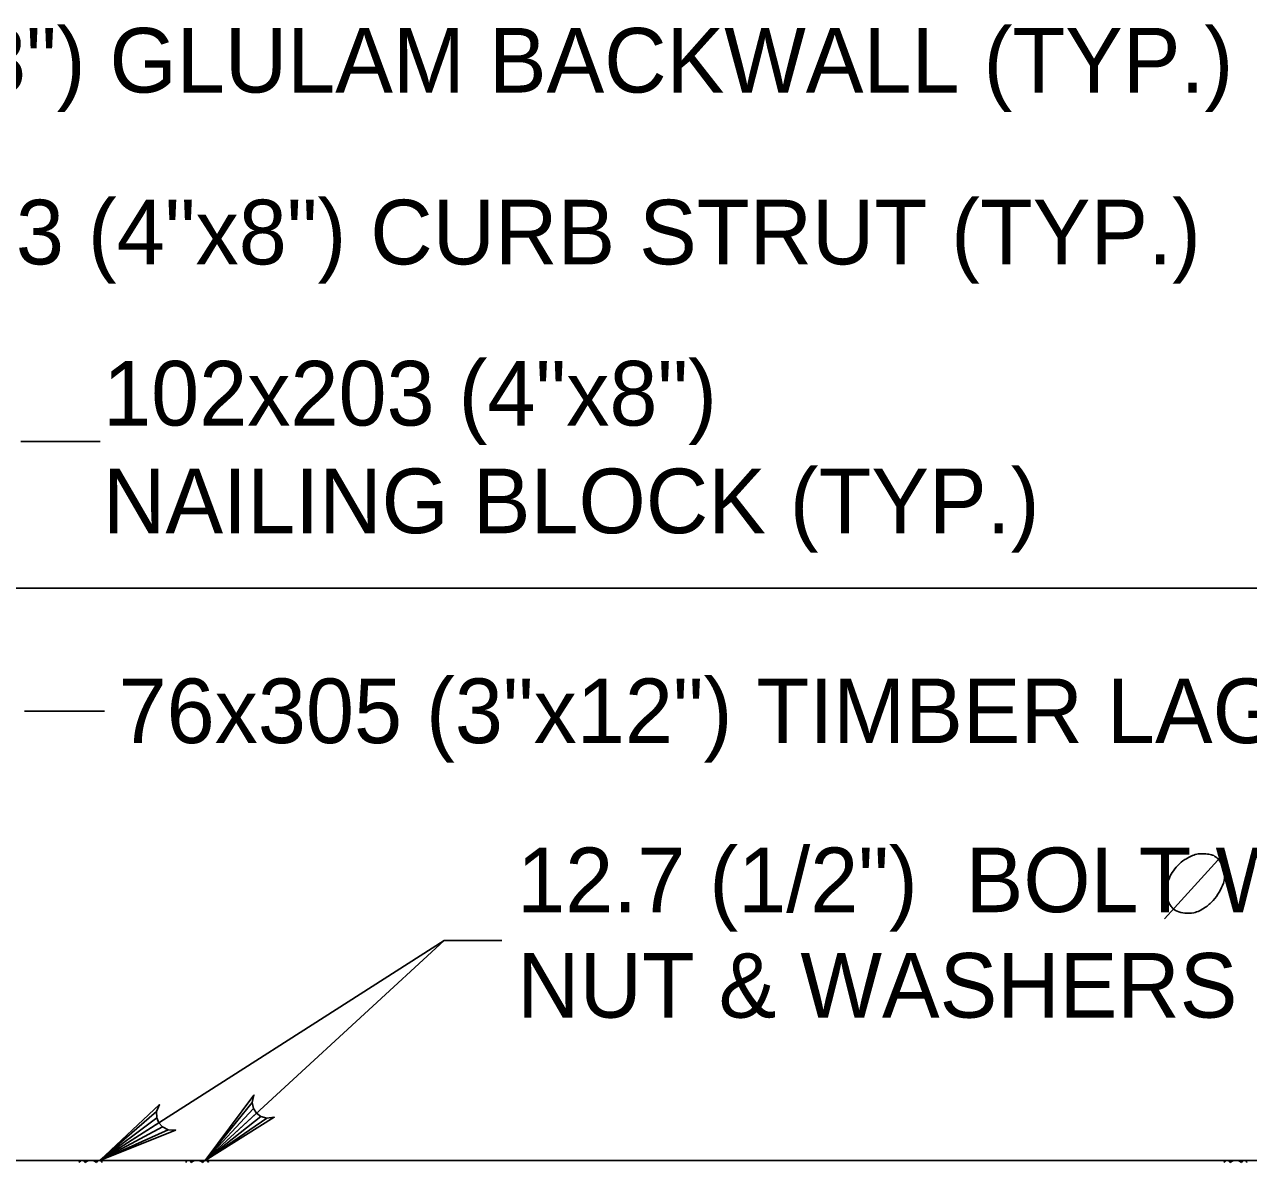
# Model space of a CAD drawing. Extents: x 635440 to 640306, y 296653 to 298484.
# Drawn here: x 639524 to 639580.8, y 297438.4 to 297491.2 of the extents above; entities that cross this region are included whole.
import ezdxf

# ---------------------------------------------------------------- set-up
doc = ezdxf.new("R2010")
doc.units = 0
for name, color, linetype in [('3', 7, 'Continuous'), ('4', 7, 'Continuous'), ('5', 7, 'Continuous'), ('52', 7, 'Continuous')]:
    doc.layers.add(name, color=color, linetype=linetype)

msp = doc.modelspace()

# ---------------------------------------------------------------- linework, layer by layer
at = {"layer": '3'}
for p, q in [((639488.268, 297465.06), (639623.868, 297465.06)), ((639467.14, 297438.486), (639623.868, 297438.486)), ((639527.454, 297438.486), (639526.645, 297438.486)), ((639526.691, 297438.482), (639526.691, 297438.482)), ((639526.706, 297438.482), (639526.706, 297438.482)), ((639526.72, 297438.482), (639526.72, 297438.482)), ((639526.729, 297438.467), (639526.729, 297438.467)), ((639526.735, 297438.482), (639526.735, 297438.482)), ((639526.743, 297438.467), (639526.743, 297438.467)), ((639526.749, 297438.482), (639526.749, 297438.482)), ((639526.749, 297438.453), (639526.749, 297438.453)), ((639526.758, 297438.467), (639526.758, 297438.467)), ((639526.764, 297438.482), (639526.764, 297438.482)), ((639526.764, 297438.453), (639526.764, 297438.453)), ((639526.772, 297438.467), (639526.772, 297438.467)), ((639526.772, 297438.438), (639526.772, 297438.438)), ((639526.781, 297438.482), (639526.781, 297438.482)), ((639526.781, 297438.453), (639526.781, 297438.453)), ((639526.781, 297438.423), (639526.781, 297438.423)), ((639526.787, 297438.467), (639526.787, 297438.467)), ((639526.787, 297438.438), (639526.787, 297438.438)), ((639526.795, 297438.482), (639526.795, 297438.482)), ((639526.795, 297438.453), (639526.795, 297438.453)), ((639526.795, 297438.423), (639526.795, 297438.423)), ((639526.801, 297438.467), (639526.801, 297438.467)), ((639526.801, 297438.438), (639526.801, 297438.438)), ((639526.81, 297438.482), (639526.81, 297438.482)), ((639526.81, 297438.453), (639526.81, 297438.453)), ((639526.81, 297438.423), (639526.81, 297438.423)), ((639526.816, 297438.467), (639526.816, 297438.467)), ((639526.816, 297438.438), (639526.816, 297438.438)), ((639526.824, 297438.482), (639526.824, 297438.482)), ((639526.824, 297438.453), (639526.824, 297438.453)), ((639526.824, 297438.423), (639526.824, 297438.423)), ((639526.831, 297438.467), (639526.831, 297438.467)), ((639526.831, 297438.438), (639526.831, 297438.438)), ((639526.839, 297438.482), (639526.839, 297438.482)), ((639526.839, 297438.453), (639526.839, 297438.453)), ((639526.845, 297438.467), (639526.845, 297438.467)), ((639526.845, 297438.438), (639526.845, 297438.438)), ((639526.854, 297438.482), (639526.854, 297438.482)), ((639526.854, 297438.453), (639526.854, 297438.453)), ((639526.86, 297438.467), (639526.86, 297438.467)), ((639526.868, 297438.482), (639526.868, 297438.482)), ((639526.868, 297438.453), (639526.868, 297438.453)), ((639526.876, 297438.467), (639526.876, 297438.467)), ((639526.883, 297438.482), (639526.883, 297438.482)), ((639526.883, 297438.453), (639526.883, 297438.453)), ((639526.889, 297438.467), (639526.889, 297438.467)), ((639526.897, 297438.482), (639526.897, 297438.482)), ((639526.906, 297438.467), (639526.906, 297438.467)), ((639526.912, 297438.482), (639526.912, 297438.482)), ((639526.92, 297438.467), (639526.92, 297438.467)), ((639526.926, 297438.482), (639526.926, 297438.482)), ((639526.941, 297438.482), (639526.941, 297438.482)), ((639526.958, 297438.482), (639526.958, 297438.482)), ((639526.972, 297438.482), (639526.972, 297438.482)), ((639526.987, 297438.482), (639526.987, 297438.482)), ((639527.118, 297438.482), (639527.118, 297438.482)), ((639527.135, 297438.482), (639527.135, 297438.482)), ((639527.149, 297438.482), (639527.149, 297438.482)), ((639527.164, 297438.482), (639527.164, 297438.482)), ((639527.179, 297438.482), (639527.179, 297438.482)), ((639527.185, 297438.467), (639527.185, 297438.467)), ((639527.193, 297438.482), (639527.193, 297438.482)), ((639527.199, 297438.467), (639527.199, 297438.467)), ((639527.208, 297438.482), (639527.208, 297438.482)), ((639527.216, 297438.467), (639527.216, 297438.467)), ((639527.222, 297438.482), (639527.222, 297438.482)), ((639527.222, 297438.453), (639527.222, 297438.453)), ((639527.231, 297438.467), (639527.231, 297438.467)), ((639527.237, 297438.482), (639527.237, 297438.482)), ((639527.237, 297438.453), (639527.237, 297438.453)), ((639527.245, 297438.467), (639527.245, 297438.467)), ((639527.251, 297438.482), (639527.251, 297438.482)), ((639527.251, 297438.453), (639527.251, 297438.453)), ((639527.26, 297438.467), (639527.26, 297438.467)), ((639527.26, 297438.438), (639527.26, 297438.438)), ((639527.268, 297438.482), (639527.268, 297438.482)), ((639527.268, 297438.453), (639527.268, 297438.453)), ((639527.274, 297438.467), (639527.274, 297438.467)), ((639527.274, 297438.438), (639527.274, 297438.438)), ((639527.281, 297438.482), (639527.281, 297438.482)), ((639527.281, 297438.453), (639527.281, 297438.453)), ((639527.281, 297438.423), (639527.281, 297438.423)), ((639527.289, 297438.467), (639527.289, 297438.467)), ((639527.289, 297438.438), (639527.289, 297438.438)), ((639527.297, 297438.482), (639527.297, 297438.482)), ((639527.297, 297438.453), (639527.297, 297438.453)), ((639527.297, 297438.423), (639527.297, 297438.423)), ((639527.304, 297438.467), (639527.304, 297438.467)), ((639527.304, 297438.438), (639527.304, 297438.438)), ((639527.312, 297438.482), (639527.312, 297438.482)), ((639527.312, 297438.453), (639527.312, 297438.453)), ((639527.312, 297438.423), (639527.312, 297438.423)), ((639527.318, 297438.467), (639527.318, 297438.467)), ((639527.318, 297438.438), (639527.318, 297438.438)), ((639527.32, 297438.467), (639527.32, 297438.467)), ((639527.32, 297438.438), (639527.32, 297438.438)), ((639527.329, 297438.482), (639527.329, 297438.482)), ((639527.329, 297438.453), (639527.329, 297438.453)), ((639527.329, 297438.423), (639527.329, 297438.423)), ((639527.335, 297438.438), (639527.335, 297438.438)), ((639527.337, 297438.467), (639527.337, 297438.467)), ((639527.343, 297438.482), (639527.343, 297438.482)), ((639527.343, 297438.453), (639527.343, 297438.453)), ((639527.349, 297438.467), (639527.349, 297438.467)), ((639527.358, 297438.482), (639527.358, 297438.482)), ((639527.358, 297438.453), (639527.358, 297438.453)), ((639527.366, 297438.467), (639527.366, 297438.467)), ((639527.372, 297438.482), (639527.372, 297438.482)), ((639527.381, 297438.467), (639527.381, 297438.467)), ((639527.387, 297438.482), (639527.387, 297438.482)), ((639527.401, 297438.482), (639527.401, 297438.482)), ((639527.418, 297438.482), (639527.418, 297438.482)), ((639531.581, 297438.486), (639532.391, 297438.486)), ((639531.618, 297438.482), (639531.618, 297438.482)), ((639531.633, 297438.482), (639531.633, 297438.482)), ((639531.647, 297438.482), (639531.647, 297438.482)), ((639531.656, 297438.467), (639531.656, 297438.467)), ((639531.662, 297438.482), (639531.662, 297438.482)), ((639531.67, 297438.467), (639531.67, 297438.467)), ((639531.677, 297438.482), (639531.677, 297438.482)), ((639531.677, 297438.453), (639531.677, 297438.453)), ((639531.685, 297438.467), (639531.685, 297438.467)), ((639531.691, 297438.482), (639531.691, 297438.482)), ((639531.691, 297438.453), (639531.691, 297438.453)), ((639531.7, 297438.467), (639531.7, 297438.467)), ((639531.7, 297438.438), (639531.7, 297438.438)), ((639531.708, 297438.482), (639531.708, 297438.482)), ((639531.708, 297438.453), (639531.708, 297438.453)), ((639531.708, 297438.423), (639531.708, 297438.423)), ((639531.714, 297438.467), (639531.714, 297438.467)), ((639531.714, 297438.438), (639531.714, 297438.438)), ((639531.716, 297438.467), (639531.716, 297438.467)), ((639531.716, 297438.438), (639531.716, 297438.438)), ((639531.725, 297438.482), (639531.725, 297438.482)), ((639531.725, 297438.453), (639531.725, 297438.453)), ((639531.725, 297438.423), (639531.725, 297438.423)), ((639531.733, 297438.467), (639531.733, 297438.467)), ((639531.733, 297438.438), (639531.733, 297438.438)), ((639531.739, 297438.482), (639531.739, 297438.482)), ((639531.739, 297438.453), (639531.739, 297438.453)), ((639531.739, 297438.423), (639531.739, 297438.423)), ((639531.745, 297438.467), (639531.745, 297438.467)), ((639531.745, 297438.438), (639531.745, 297438.438)), ((639531.754, 297438.482), (639531.754, 297438.482)), ((639531.754, 297438.453), (639531.754, 297438.453)), ((639531.754, 297438.423), (639531.754, 297438.423)), ((639531.76, 297438.467), (639531.76, 297438.467)), ((639531.76, 297438.438), (639531.76, 297438.438)), ((639531.768, 297438.482), (639531.768, 297438.482)), ((639531.768, 297438.453), (639531.768, 297438.453)), ((639531.777, 297438.467), (639531.777, 297438.467)), ((639531.777, 297438.438), (639531.777, 297438.438)), ((639531.783, 297438.482), (639531.783, 297438.482)), ((639531.783, 297438.453), (639531.783, 297438.453)), ((639531.791, 297438.467), (639531.791, 297438.467)), ((639531.797, 297438.482), (639531.797, 297438.482)), ((639531.797, 297438.453), (639531.797, 297438.453)), ((639531.806, 297438.467), (639531.806, 297438.467)), ((639531.812, 297438.482), (639531.812, 297438.482)), ((639531.812, 297438.453), (639531.812, 297438.453)), ((639531.82, 297438.467), (639531.82, 297438.467)), ((639531.827, 297438.482), (639531.827, 297438.482)), ((639531.835, 297438.467), (639531.835, 297438.467)), ((639531.841, 297438.482), (639531.841, 297438.482)), ((639531.85, 297438.467), (639531.85, 297438.467)), ((639531.858, 297438.482), (639531.858, 297438.482)), ((639531.873, 297438.482), (639531.873, 297438.482)), ((639531.887, 297438.482), (639531.887, 297438.482)), ((639531.902, 297438.482), (639531.902, 297438.482)), ((639531.916, 297438.482), (639531.916, 297438.482)), ((639532.05, 297438.482), (639532.05, 297438.482)), ((639532.064, 297438.482), (639532.064, 297438.482)), ((639532.079, 297438.482), (639532.079, 297438.482)), ((639532.093, 297438.482), (639532.093, 297438.482)), ((639532.108, 297438.482), (639532.108, 297438.482)), ((639532.116, 297438.467), (639532.116, 297438.467)), ((639532.123, 297438.482), (639532.123, 297438.482)), ((639532.131, 297438.467), (639532.131, 297438.467)), ((639532.137, 297438.482), (639532.137, 297438.482)), ((639532.145, 297438.467), (639532.145, 297438.467)), ((639532.152, 297438.482), (639532.152, 297438.482)), ((639532.152, 297438.453), (639532.152, 297438.453)), ((639532.16, 297438.467), (639532.16, 297438.467)), ((639532.168, 297438.482), (639532.168, 297438.482)), ((639532.168, 297438.453), (639532.168, 297438.453)), ((639532.175, 297438.467), (639532.175, 297438.467)), ((639532.181, 297438.482), (639532.181, 297438.482)), ((639532.181, 297438.453), (639532.181, 297438.453)), ((639532.189, 297438.467), (639532.189, 297438.467)), ((639532.189, 297438.438), (639532.189, 297438.438)), ((639532.195, 297438.482), (639532.195, 297438.482)), ((639532.195, 297438.453), (639532.195, 297438.453)), ((639532.204, 297438.467), (639532.204, 297438.467)), ((639532.204, 297438.438), (639532.204, 297438.438)), ((639532.212, 297438.482), (639532.212, 297438.482)), ((639532.212, 297438.453), (639532.212, 297438.453)), ((639532.212, 297438.423), (639532.212, 297438.423)), ((639532.218, 297438.467), (639532.218, 297438.467)), ((639532.218, 297438.438), (639532.218, 297438.438)), ((639532.227, 297438.482), (639532.227, 297438.482)), ((639532.227, 297438.453), (639532.227, 297438.453)), ((639532.227, 297438.423), (639532.227, 297438.423)), ((639532.233, 297438.467), (639532.233, 297438.467)), ((639532.233, 297438.438), (639532.233, 297438.438)), ((639532.241, 297438.482), (639532.241, 297438.482)), ((639532.241, 297438.453), (639532.241, 297438.453)), ((639532.241, 297438.423), (639532.241, 297438.423)), ((639532.248, 297438.467), (639532.248, 297438.467)), ((639532.248, 297438.438), (639532.248, 297438.438)), ((639532.256, 297438.482), (639532.256, 297438.482)), ((639532.256, 297438.453), (639532.256, 297438.453)), ((639532.256, 297438.423), (639532.256, 297438.423)), ((639532.262, 297438.438), (639532.262, 297438.438)), ((639532.264, 297438.467), (639532.264, 297438.467)), ((639532.27, 297438.482), (639532.27, 297438.482)), ((639532.27, 297438.453), (639532.27, 297438.453)), ((639532.277, 297438.467), (639532.277, 297438.467)), ((639532.285, 297438.482), (639532.285, 297438.482)), ((639532.285, 297438.453), (639532.285, 297438.453)), ((639532.293, 297438.467), (639532.293, 297438.467)), ((639532.3, 297438.482), (639532.3, 297438.482)), ((639532.308, 297438.467), (639532.308, 297438.467)), ((639532.314, 297438.482), (639532.314, 297438.482)), ((639532.329, 297438.482), (639532.329, 297438.482)), ((639532.345, 297438.482), (639532.345, 297438.482)), ((639580.606, 297438.488), (639579.798, 297438.488)), ((639579.843, 297438.484), (639579.843, 297438.484)), ((639579.858, 297438.484), (639579.858, 297438.484)), ((639579.873, 297438.484), (639579.873, 297438.484)), ((639579.879, 297438.469), (639579.879, 297438.469)), ((639579.887, 297438.484), (639579.887, 297438.484)), ((639579.896, 297438.469), (639579.896, 297438.469)), ((639579.902, 297438.484), (639579.902, 297438.484)), ((639579.902, 297438.455), (639579.902, 297438.455)), ((639579.91, 297438.469), (639579.91, 297438.469)), ((639579.916, 297438.484), (639579.916, 297438.484)), ((639579.916, 297438.455), (639579.916, 297438.455)), ((639579.925, 297438.469), (639579.925, 297438.469)), ((639579.925, 297438.44), (639579.925, 297438.44)), ((639579.931, 297438.484), (639579.931, 297438.484)), ((639579.931, 297438.455), (639579.931, 297438.455)), ((639579.931, 297438.426), (639579.931, 297438.426)), ((639579.939, 297438.469), (639579.939, 297438.469)), ((639579.939, 297438.44), (639579.939, 297438.44)), ((639579.948, 297438.484), (639579.948, 297438.484)), ((639579.948, 297438.455), (639579.948, 297438.455)), ((639579.948, 297438.426), (639579.948, 297438.426)), ((639579.954, 297438.469), (639579.954, 297438.469)), ((639579.954, 297438.44), (639579.954, 297438.44)), ((639579.96, 297438.484), (639579.96, 297438.484)), ((639579.96, 297438.455), (639579.96, 297438.455)), ((639579.96, 297438.426), (639579.96, 297438.426)), ((639579.968, 297438.469), (639579.968, 297438.469)), ((639579.968, 297438.44), (639579.968, 297438.44)), ((639579.975, 297438.484), (639579.975, 297438.484)), ((639579.975, 297438.455), (639579.975, 297438.455)), ((639579.975, 297438.426), (639579.975, 297438.426)), ((639579.983, 297438.469), (639579.983, 297438.469)), ((639579.983, 297438.44), (639579.983, 297438.44)), ((639579.991, 297438.484), (639579.991, 297438.484)), ((639579.991, 297438.455), (639579.991, 297438.455)), ((639579.998, 297438.469), (639579.998, 297438.469)), ((639579.998, 297438.44), (639579.998, 297438.44)), ((639580.006, 297438.484), (639580.006, 297438.484)), ((639580.006, 297438.455), (639580.006, 297438.455)), ((639580.012, 297438.469), (639580.012, 297438.469)), ((639580.021, 297438.484), (639580.021, 297438.484)), ((639580.021, 297438.455), (639580.021, 297438.455)), ((639580.027, 297438.469), (639580.027, 297438.469)), ((639580.035, 297438.484), (639580.035, 297438.484)), ((639580.035, 297438.455), (639580.035, 297438.455)), ((639580.041, 297438.469), (639580.041, 297438.469)), ((639580.05, 297438.484), (639580.05, 297438.484)), ((639580.056, 297438.469), (639580.056, 297438.469)), ((639580.064, 297438.484), (639580.064, 297438.484)), ((639580.073, 297438.469), (639580.073, 297438.469)), ((639580.079, 297438.484), (639580.079, 297438.484)), ((639580.093, 297438.484), (639580.093, 297438.484)), ((639580.108, 297438.484), (639580.108, 297438.484)), ((639580.125, 297438.484), (639580.125, 297438.484)), ((639580.137, 297438.484), (639580.137, 297438.484)), ((639580.271, 297438.484), (639580.271, 297438.484)), ((639580.285, 297438.484), (639580.285, 297438.484)), ((639580.302, 297438.484), (639580.302, 297438.484)), ((639580.314, 297438.484), (639580.314, 297438.484)), ((639580.331, 297438.484), (639580.331, 297438.484)), ((639580.337, 297438.469), (639580.337, 297438.469)), ((639580.346, 297438.484), (639580.346, 297438.484)), ((639580.352, 297438.469), (639580.352, 297438.469)), ((639580.36, 297438.484), (639580.36, 297438.484)), ((639580.366, 297438.469), (639580.366, 297438.469)), ((639580.375, 297438.484), (639580.375, 297438.484)), ((639580.375, 297438.455), (639580.375, 297438.455)), ((639580.383, 297438.469), (639580.383, 297438.469)), ((639580.389, 297438.484), (639580.389, 297438.484)), ((639580.389, 297438.455), (639580.389, 297438.455)), ((639580.396, 297438.469), (639580.396, 297438.469)), ((639580.404, 297438.484), (639580.404, 297438.484)), ((639580.404, 297438.455), (639580.404, 297438.455)), ((639580.41, 297438.469), (639580.41, 297438.469)), ((639580.41, 297438.44), (639580.41, 297438.44)), ((639580.418, 297438.484), (639580.418, 297438.484)), ((639580.418, 297438.455), (639580.418, 297438.455)), ((639580.427, 297438.469), (639580.427, 297438.469)), ((639580.427, 297438.44), (639580.427, 297438.44)), ((639580.433, 297438.484), (639580.433, 297438.484)), ((639580.433, 297438.455), (639580.433, 297438.455)), ((639580.433, 297438.426), (639580.433, 297438.426)), ((639580.441, 297438.469), (639580.441, 297438.469)), ((639580.441, 297438.44), (639580.441, 297438.44)), ((639580.448, 297438.484), (639580.448, 297438.484)), ((639580.448, 297438.455), (639580.448, 297438.455)), ((639580.448, 297438.426), (639580.448, 297438.426)), ((639580.456, 297438.469), (639580.456, 297438.469)), ((639580.456, 297438.44), (639580.456, 297438.44)), ((639580.462, 297438.484), (639580.462, 297438.484)), ((639580.462, 297438.455), (639580.462, 297438.455)), ((639580.462, 297438.426), (639580.462, 297438.426)), ((639580.471, 297438.469), (639580.471, 297438.469)), ((639580.471, 297438.44), (639580.471, 297438.44)), ((639580.473, 297438.469), (639580.473, 297438.469)), ((639580.473, 297438.44), (639580.473, 297438.44)), ((639580.481, 297438.484), (639580.481, 297438.484)), ((639580.481, 297438.455), (639580.481, 297438.455)), ((639580.481, 297438.426), (639580.481, 297438.426)), ((639580.487, 297438.469), (639580.487, 297438.469)), ((639580.487, 297438.44), (639580.487, 297438.44)), ((639580.496, 297438.484), (639580.496, 297438.484)), ((639580.496, 297438.455), (639580.496, 297438.455)), ((639580.502, 297438.469), (639580.502, 297438.469)), ((639580.51, 297438.484), (639580.51, 297438.484)), ((639580.51, 297438.455), (639580.51, 297438.455)), ((639580.516, 297438.469), (639580.516, 297438.469)), ((639580.525, 297438.484), (639580.525, 297438.484)), ((639580.533, 297438.469), (639580.533, 297438.469)), ((639580.539, 297438.484), (639580.539, 297438.484)), ((639580.554, 297438.484), (639580.554, 297438.484)), ((639580.568, 297438.484), (639580.568, 297438.484)), ((639526.787, 297438.409), (639526.787, 297438.409)), ((639526.801, 297438.409), (639526.801, 297438.409)), ((639527.304, 297438.409), (639527.304, 297438.409)), ((639527.318, 297438.409), (639527.318, 297438.409)), ((639527.32, 297438.409), (639527.32, 297438.409)), ((639531.714, 297438.409), (639531.714, 297438.409)), ((639531.716, 297438.409), (639531.716, 297438.409)), ((639531.733, 297438.409), (639531.733, 297438.409)), ((639532.233, 297438.409), (639532.233, 297438.409)), ((639532.248, 297438.409), (639532.248, 297438.409)), ((639579.939, 297438.411), (639579.939, 297438.411)), ((639579.954, 297438.411), (639579.954, 297438.411)), ((639580.456, 297438.411), (639580.456, 297438.411)), ((639580.471, 297438.411), (639580.471, 297438.411)), ((639580.473, 297438.411), (639580.473, 297438.411))]:
    msp.add_line(p, q, dxfattribs=at)
for centre, radius, start, end in [((639526.651, 297438.341), 0.148, 88.1729, 158.7131), ((639526.651, 297438.341), 0.148, 21.2869, 88.1729), ((639527.055, 297438.065), 0.424, 51.05, 128.95), ((639527.45, 297438.354), 0.135, 17.4518, 162.5482), ((639531.587, 297438.354), 0.135, 17.4518, 162.5482), ((639531.982, 297438.065), 0.424, 51.05, 128.95), ((639532.387, 297438.341), 0.148, 91.8271, 158.7131), ((639532.387, 297438.341), 0.148, 21.2869, 91.8271), ((639579.801, 297438.341), 0.148, 88.1729, 158.7131), ((639579.801, 297438.341), 0.148, 21.2869, 88.1729), ((639580.206, 297438.065), 0.424, 51.05, 128.95), ((639580.601, 297438.354), 0.135, 17.4518, 162.5482)]:
    msp.add_arc(centre, radius, start, end, dxfattribs=at)
at = {"layer": '4'}
for p, q in [((639523.802, 297471.866), (639527.491, 297471.866)), ((639523.975, 297459.344), (639527.693, 297459.344))]:
    msp.add_line(p, q, dxfattribs=at)
for points in [[(639527.476, 297438.484), (639543.463, 297448.707)], [(639532.356, 297438.486), (639543.463, 297448.707), (639546.129, 297448.707)]]:
    msp.add_lwpolyline(points, dxfattribs=at)
at = {"layer": '5'}
msp.add_line((639576.889, 297449.709), (639579.689, 297452.774), dxfattribs=at)
msp.add_spline([(639579.398, 297452.472), (639579.179, 297452.643), (639578.96, 297452.703), (639578.685, 297452.728), (639578.529, 297452.728), (639578.26, 297452.666), (639578.014, 297452.553), (639577.841, 297452.455), (639577.51, 297452.191), (639577.252, 297451.853), (639577.095, 297451.537), (639577.004, 297451.247), (639576.977, 297450.978), (639577.004, 297450.747), (639577.116, 297450.418), (639577.235, 297450.247), (639577.477, 297450.066), (639577.839, 297449.978), (639578.252, 297449.991), (639578.773, 297450.228), (639579.154, 297450.555), (639579.441, 297450.953), (639579.629, 297451.368), (639579.691, 297451.828), (639579.61, 297452.124), (639579.41, 297452.472)], degree=3, dxfattribs=at)
at = {"layer": '52'}
for points in [[(639532.356, 297438.486), (639534.627, 297441.526), (639534.55, 297441.184), (639534.61, 297440.901), (639534.748, 297440.686), (639534.948, 297440.532), (639535.227, 297440.449), (639535.573, 297440.496), (639532.356, 297438.486), (639535.227, 297440.449), (639534.948, 297440.532), (639532.356, 297438.486), (639534.748, 297440.686), (639534.61, 297440.901), (639532.356, 297438.486), (639534.55, 297441.184)], [(639527.476, 297438.484), (639530.241, 297441.082), (639530.106, 297440.759), (639530.116, 297440.469), (639530.214, 297440.234), (639530.385, 297440.046), (639530.645, 297439.917), (639530.993, 297439.903), (639527.476, 297438.484), (639530.645, 297439.917), (639530.385, 297440.046), (639527.476, 297438.484), (639530.214, 297440.234), (639530.116, 297440.469), (639527.476, 297438.484), (639530.106, 297440.759)]]:
    msp.add_lwpolyline(points, dxfattribs=at)

# ---------------------------------------------------------------- texts
at = {"layer": '4'}
for s, p in [('12.7 (1/2")  BOLT W/ STD.', (639546.844, 297450.016)), ('NUT & WASHERS (TYP.)', (639546.844, 297445.12))]:
    msp.add_text(s, height=3.00014, dxfattribs=at).set_placement(p)
at = {"layer": '5'}
for s, p in [('79 (3 1/8") GLULAM BACKWALL (TYP.)', (639508.211, 297488.067)), ('102x203 (4"x8") CURB STRUT (TYP.)', (639510.415, 297480.09)), ('102x203 (4"x8")', (639527.622, 297472.608)), ('NAILING BLOCK (TYP.)', (639527.622, 297467.608)), ('76x305 (3"x12") TIMBER LAGGING ABUT.', (639528.341, 297457.864))]:
    msp.add_text(s, height=3.00014, dxfattribs=at).set_placement(p)

doc.saveas('drawing.dxf')
